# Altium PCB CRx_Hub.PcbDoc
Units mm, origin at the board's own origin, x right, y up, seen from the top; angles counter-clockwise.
Board outline 66.93 x 64.01 mm, 2 copper layers (Top Layer, Bottom Layer); 10 components, 18 nets, 60 pads, 0 vias.
Unrouted connection lines stored in the file: 2.
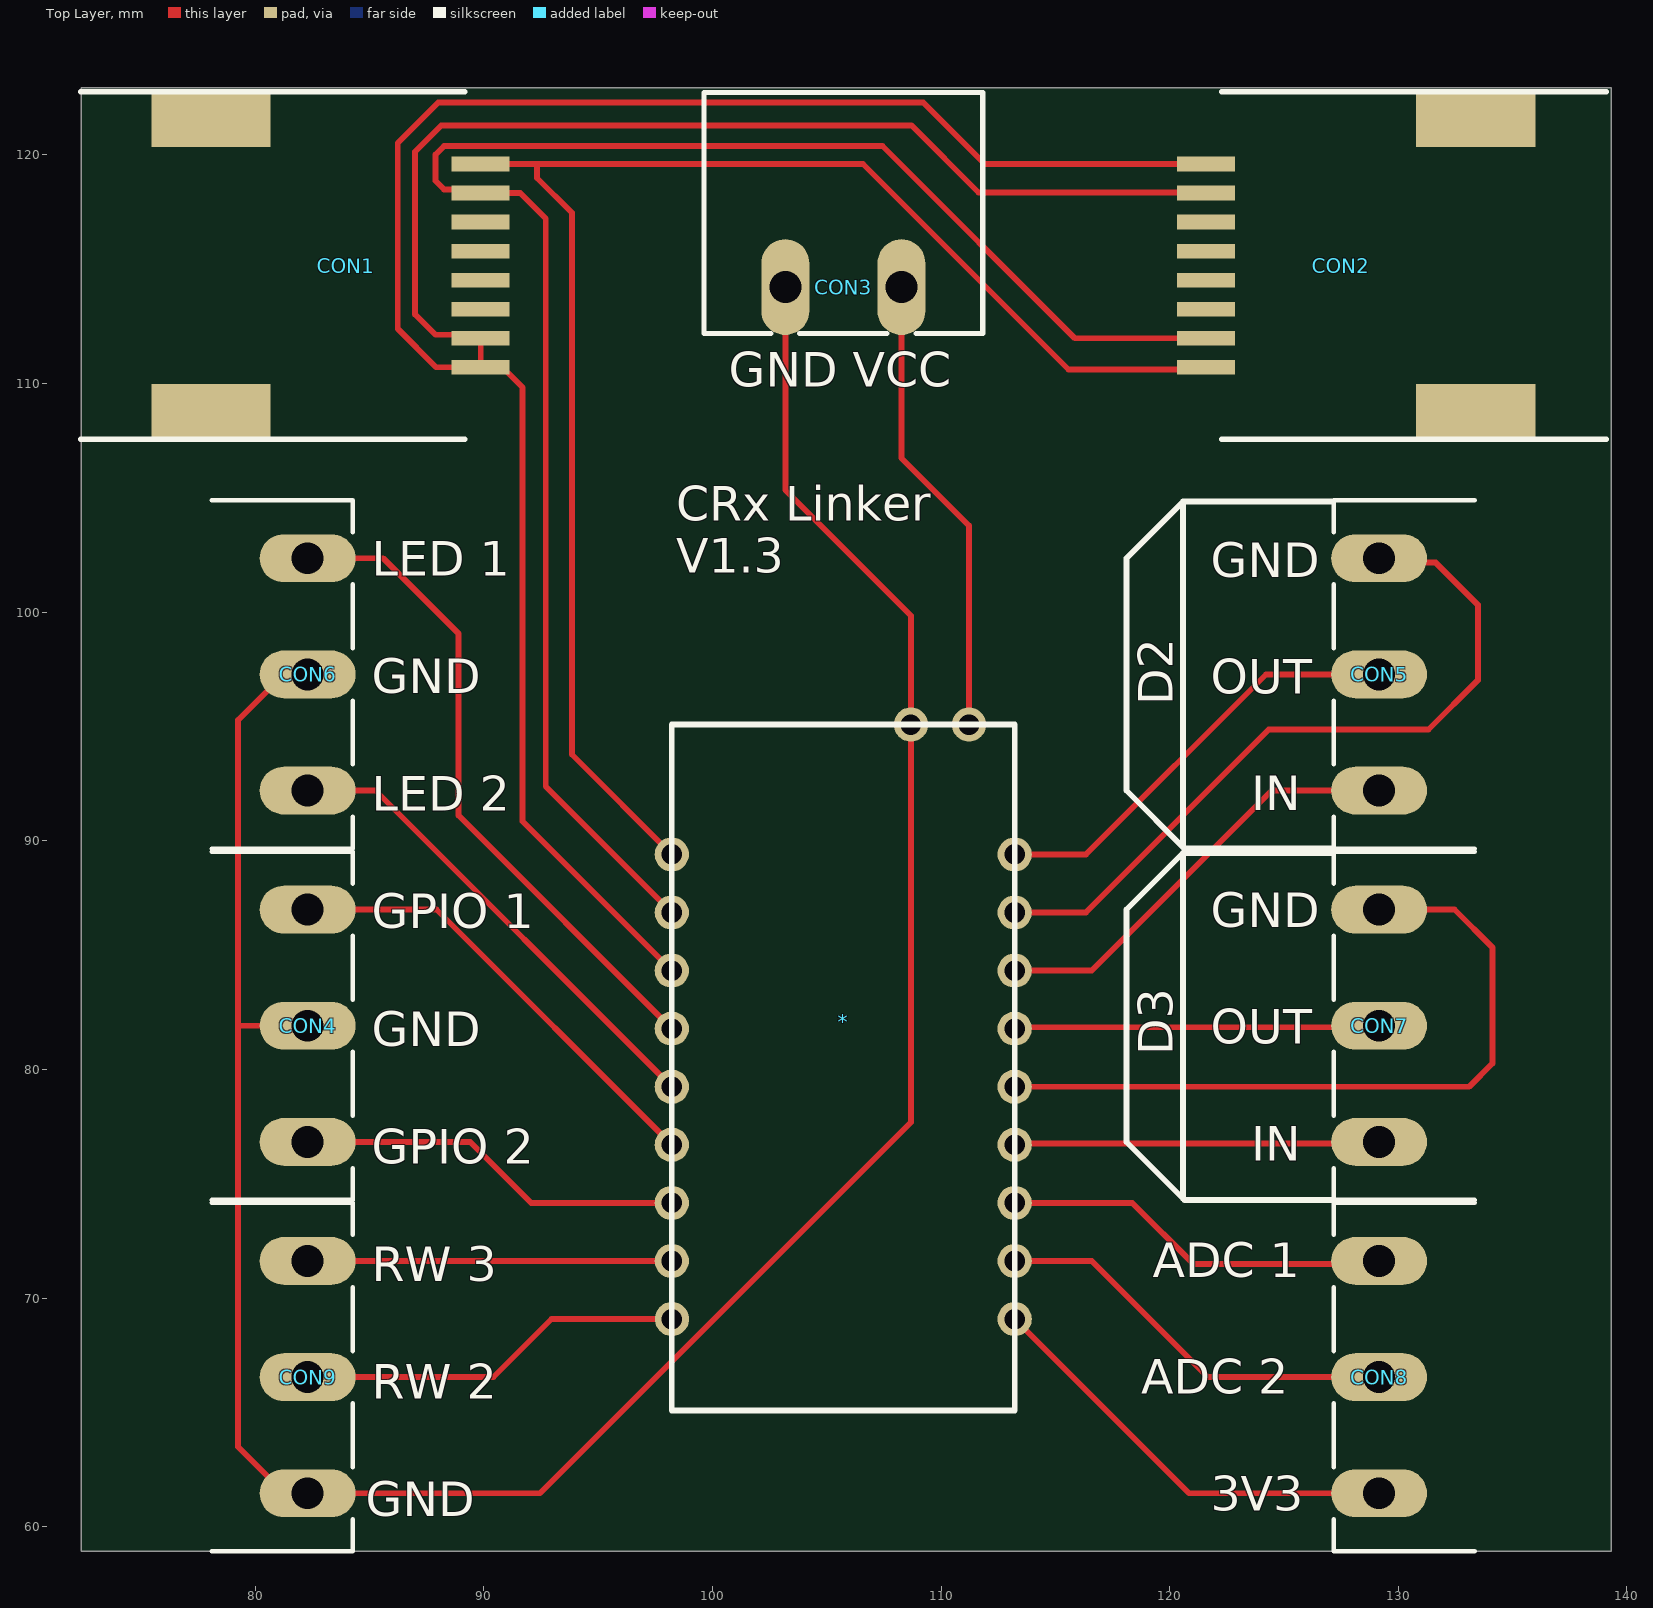
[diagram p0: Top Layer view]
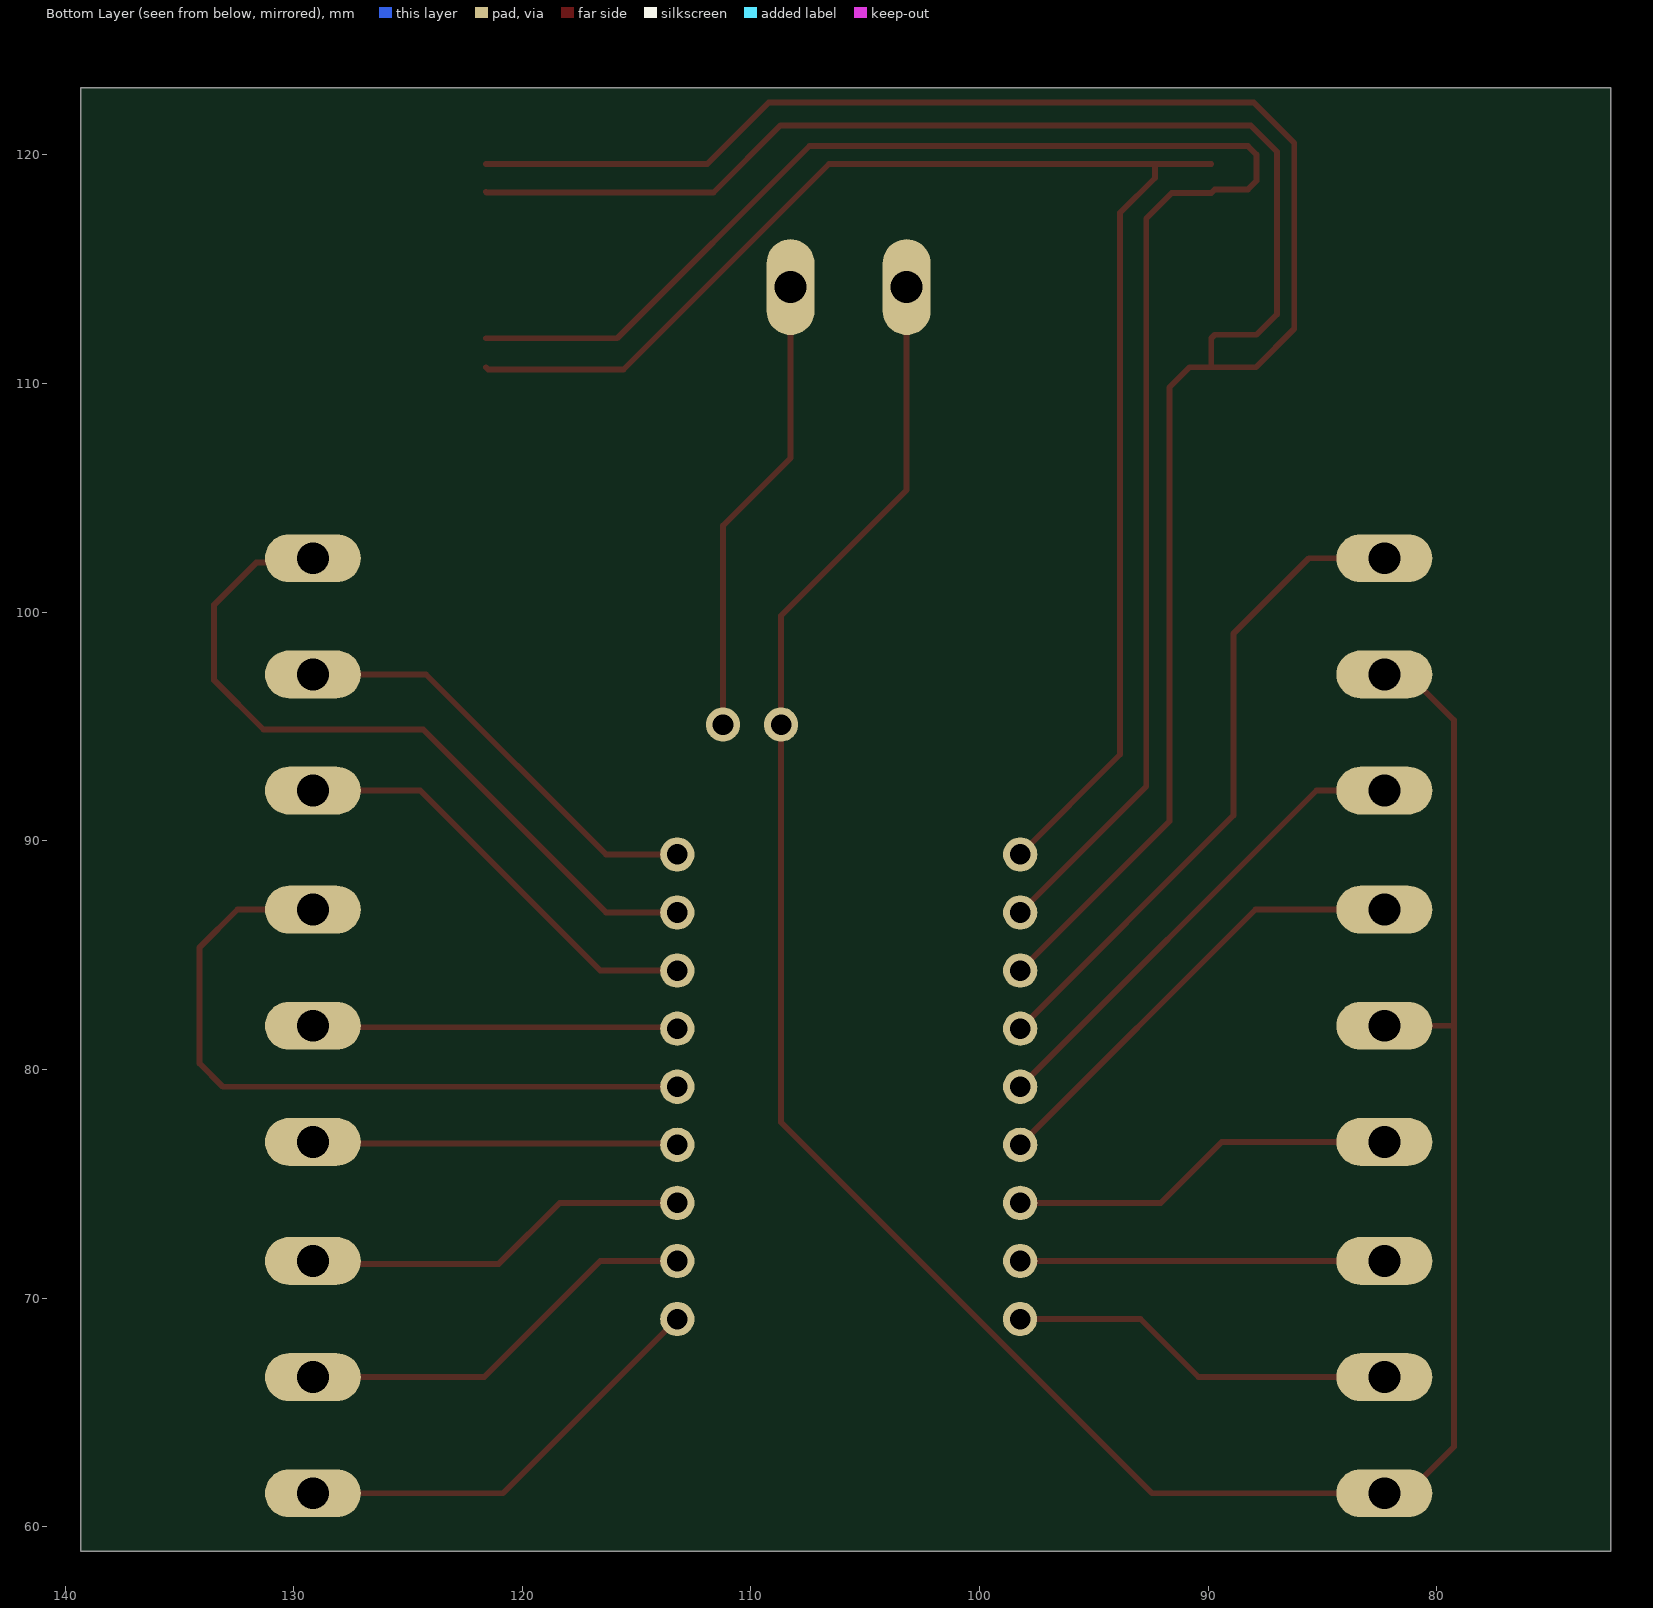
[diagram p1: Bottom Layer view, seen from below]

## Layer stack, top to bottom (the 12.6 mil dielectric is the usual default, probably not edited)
Top Solder: solder mask 0.0102, Solder Resist, Dk 3.5
Top Layer: signal copper 0.0356
Dielectric 1: dielectric 0.32, FR-4, Dk 4.8
Bottom Layer: signal copper 0.0356
Bottom Solder: solder mask 0.0102, Solder Resist, Dk 3.5

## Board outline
72.39,58.928 139.319,58.928 139.319,122.936 72.39,122.936

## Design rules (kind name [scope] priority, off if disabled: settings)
Clearance [All] p1: gap=0.254 ignorepadtopadclearanceinfootprint=FALSE except(0: Arc-Hole Track-Hole SMDPad-Hole THPad-Hole Via-Hole Fill-Hole Poly-Hole Region-Hole Text-Hole)
PolygonConnect [All] p1: connectstyle=Relief reliefconductorwidth=0.254 reliefentries=4 polygonreliefangle="90 Angle" airgapwidth=0.254
RoomDefinition CRx_Hub [InComponentClass('CRx_Hub')] p1: confinementstyle=ConfineIn formatcopy=TRUE lockcomponents=FALSE outline 178.943,26.797 210.058,26.797 210.058,83.439 178.943,83.439
RoutingVias [All] p1: holewidth=0.711 width=1.27 viastyle="Through Hole" minholewidth=0.711 minwidth=1.27 maxholewidth=0.711 maxwidth=1.27
SolderMaskExpansion [All] p1: expansion=0.102 istentingtop=FALSE
Width [All] p1: maxlimit=0.254 minlimit=0.254 preferedwidth=0.254
30 further rules are at their usual default settings.

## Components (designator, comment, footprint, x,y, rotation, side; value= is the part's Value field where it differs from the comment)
* "CRX-OEM" CRX_OEM-THRU 105.722,80.088 r0 top
CON1 "44144-0003" 44144_0003 89.865,115.162 r180 top
CON2 "44144-0003" 44144_0003 121.59,115.162 r0 top
CON3 "1759444" MSTBA2 105.729,119.301 r180 top
CON4 "1759512" "MSTB 2,5/ 3-G-5,08 BK" 77.216,81.915 r270 top
CON5 "1759512" "MSTB 2,5/ 3-G-5,08 BK" 134.239,97.282 r90 top
CON6 "1759512" "MSTB 2,5/ 3-G-5,08 BK" 77.216,97.282 r270 top
CON7 "1759512" "MSTB 2,5/ 3-G-5,08 BK" 134.239,81.915 r90 top
CON8 "1759512" "MSTB 2,5/ 3-G-5,08 BK" 134.239,66.548 r90 top
CON9 "1759512" "MSTB 2,5/ 3-G-5,08 BK" 77.216,66.548 r270 top

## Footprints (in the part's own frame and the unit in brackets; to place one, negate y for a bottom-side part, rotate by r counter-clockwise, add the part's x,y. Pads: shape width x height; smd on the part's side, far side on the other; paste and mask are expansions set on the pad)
44144_0003 [mm]
  rect 5.21x2.54 smd: 0(11.795,6.45) 0(11.795,-6.45)
  rect 2.54x0.64 smd: 1(0,-4.445) 2(0,-3.175) 3(0,-1.905) 4(0,-0.635) 5(0,0.635) 6(0,1.905) 7(0,3.175) 8(0,4.445)
  silkscreen extent 0.69,-7.6 17.5,7.6, body extent -0.94,-7.62 17.45,7.62, height 11.7
CRX_OEM-THRU [mm] "CRX OEM Version Thru hole connection"
  round 1.5 hole 0.9: 1(7.5,-11) 2(7.5,-8.46) 3(7.5,-5.92) 4(7.5,-3.38) 5(7.5,-0.84) 6(7.5,1.7) 7(7.5,4.24) 8(7.5,6.78) 9(7.5,9.32) 10(5.5,15) 11(2.96,15) 12(-7.5,9.32) 13(-7.5,6.78) 14(-7.5,4.24) 15(-7.5,1.7) 16(-7.5,-0.84) 17(-7.5,-3.38) 18(-7.5,-5.92) 19(-7.5,-8.46) 20(-7.493,-11)
  silkscreen extent -7.5,-15 7.5,15, body extent -8.78,-15 8.76,16.26, height 5.69
"MSTB 2,5/ 3-G-5,08 BK" [mil]
  oval 82.48x165 hole 55: 1(-200,200) 2(0,200) 3(200,200)
  silkscreen extent -300,35 300,278, body extent -300,-196 300,277, height 339
MSTBA2 [mil]
  oval 82.48x165 hole 55: 1(-100,200) 2(100,200)
  silkscreen extent -240,-135 240,280, body extent -240,-225 240,280, height 300

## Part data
*: "CRX OEM module"
CON1 CON2: library part 44144_0003, "Modular Connector, RJ45, Jack, 8 Contacts, 8 Ways, 44144 Series, Cat3", Manufacturer 1=Molex, Supplier Part Number 1=2063741
CON3: library part "MSTB 2,5/ 2-G-5,08 BK", "Pluggable Terminal Blocks 2 Pos 5.08mm pitch Through Hole Header", Manufacturer 1="Phoenix Contact"
CON4 CON5 CON6 CON7 CON8 CON9: library part "MSTB 2,5/ 3-G-5,08 BK", "PCB headers, nominal current: 12 A, rated voltage (III/2): 320 V, number of positions: 3, pitch: 5.08 mm, color: black, contact surface: Tin, mounting: Wave soldering", Color=Black, Manufacturer 1="Phoenix Contact"

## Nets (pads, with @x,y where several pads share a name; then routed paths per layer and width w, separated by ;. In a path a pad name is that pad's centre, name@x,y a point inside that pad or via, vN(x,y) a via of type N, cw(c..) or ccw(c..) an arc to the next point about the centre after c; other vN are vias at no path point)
Net*_1: *.1 CON8.1 | length 19.1
  Top Layer w0.254: *.1 120.842,61.468 CON8.1
Net*_2: *.2 CON8.2 | length 18
  Top Layer w0.254: *.2 116.586,71.628 121.666,66.548 CON8.2
Net*_3: *.3 CON8.3 | length 17.1
  Top Layer w0.254: *.3 118.364,74.168 121.031,71.501 129.032,71.501 CON8.3
Net*_4: *.4 CON7.1 | length 16
  Top Layer w0.254: *.4 113.285,76.772 129.095,76.772 CON7.1
Net*_5: *.5 *.8 *.11 CON3.2 CON4.2 CON5.3 CON6.2 CON7.3 CON9.3 | length 179.6
  Top Layer w0.254: CON4.2 79.248,81.915 ; CON6.2 81.248,97.282 79.248,95.282 79.248,81.915 ; CON3.2 103.189,105.345 108.682,99.852 *.11 108.682,77.694 92.456,61.468 CON9.3 82.07,61.242 81.844,61.468 81.28,61.468 79.248,63.5 79.248,81.915 ; *.5 133.096,79.248 134.112,80.264 134.112,85.344 132.461,86.995 CON7.3 ; *.8 116.332,86.868 124.333,94.869 131.318,94.869 133.477,97.028 133.477,100.33 131.636,102.171 129.35,102.171 CON5.3
Net*_6: *.6 CON7.2 | length 16
  Top Layer w0.254: *.6 113.285,81.852 129.095,81.852 CON7.2
Net*_7: *.7 CON5.1 | length 19.2
  Top Layer w0.254: *.7 116.586,84.328 124.46,92.202 CON5.1
Net*_9: *.9 CON5.2 | length 19.2
  Top Layer w0.254: *.9 116.332,89.408 124.206,97.282 CON5.2
Net*_10: *.10 CON3.1 | length 20.4
  Top Layer w0.254: CON3.1 108.269,106.742 111.222,103.789 *.10
Net*_12: *.12 CON1.1 CON2.1 | length 68.1
  Top Layer w0.254: CON1.1 91.721,119.607 92.329,119.607 ; *.12 93.853,93.777 93.853,117.475 92.329,118.999 92.329,119.607 ; CON2.1 121.49,110.617 115.57,110.617 106.58,119.607 92.329,119.607
Net*_13: *.13 CON1.2 CON2.2 | length 76.6
  Top Layer w0.254: *.13 92.71,92.38 92.71,117.221 91.594,118.337 CON1.2 89.711,118.491 88.265,118.491 87.884,118.872 87.884,120.015 88.265,120.396 107.442,120.396 115.851,111.987 CON2.2
Net*_14: *.14 CON1.7 CON1.8 CON2.7 CON2.8 | length 128
  Top Layer w0.254: *.14 91.694,90.856 91.694,109.838 90.815,110.717 CON1.8 ; CON2.7@121.59,118.391 121.563,118.364 111.633,118.364 108.712,121.285 88.138,121.285 86.995,120.142 86.995,113.03 87.884,112.141 89.711,112.141 CON1.7 CON1.8 ; CON2.8 111.914,119.607 109.22,122.301 88.011,122.301 86.233,120.523 86.233,112.395 87.911,110.717 CON1.8
Net*_15: *.15 CON6.1 | length 29.1
  Top Layer w0.254: CON6.1 85.598,102.362 88.9,99.06 88.9,91.11 *.15
Net*_16: *.16 CON6.3 | length 21.3
  Top Layer w0.254: CON6.3 85.268,92.202 *.16
Net*_17: *.17 CON4.1 | length 20.2
  Top Layer w0.254: CON4.1 87.935,86.995 *.17
Net*_18: *.18 CON4.3 | length 17
  Top Layer w0.254: CON4.3 89.408,76.835 92.075,74.168 *.18
Net*_19: *.19 CON9.1 | length 15.9
  Top Layer w0.254: CON9.1 *.19
Net*_20: *.20 CON9.2 | length 17
  Top Layer w0.254: CON9.2 90.424,66.548 92.964,69.088 *.20
pads on no net: CON1.0 CON1.3 CON1.4 CON1.5 CON1.6 CON2.0 CON2.3 CON2.4 CON2.5 CON2.6

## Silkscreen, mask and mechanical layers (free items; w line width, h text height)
Top Overlay:
  lines w0.254: 120.587,74.358 120.587,89.471 ; 120.587,89.725 120.587,104.838 ; 127.178,74.295 120.65,74.295 118.11,76.835 118.11,86.995 120.587,89.471 ; 127.178,89.471 120.587,89.471 ; 127.178,89.662 120.65,89.662 118.11,92.202 118.11,102.362 120.587,104.838 ; 127.178,104.838 120.587,104.838
  text "GND VCC" at 100.711,109.855 h1.52
  text "CRx Linker / V1.3" at 98.425,101.727 h1.52
  text "LED 1" at 85.09,101.6 h1.52
  text "GND" at 121.792,101.539 h1.52
  text "GND" at 85.09,96.456 h1.52
  text "OUT" at 121.792,96.435 h1.52
  text "D2" at 120.142,95.927 h1.52 r90
  text "IN" at 123.569,91.331 h1.52
  text "LED 2" at 85.09,91.313 h1.52
  text "GND" at 121.792,86.227 h1.52
  text "GPIO 1" at 85.09,86.169 h1.52
  text "OUT" at 121.792,81.123 h1.52
  text "GND" at 85.09,81.026 h1.52
  text "D3" at 120.142,80.615 h1.52 r90
  text "IN" at 123.569,76.019 h1.52
  text "GPIO 2" at 85.09,75.882 h1.52
  text "ADC 1" at 119.253,70.914 h1.52
  text "RW 3" at 85.09,70.739 h1.52
  text "ADC 2" at 118.745,65.81 h1.52
  text "RW 2" at 85.09,65.596 h1.52
  text "3V3" at 121.793,60.706 h1.52
  text "GND" at 84.836,60.452 h1.52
